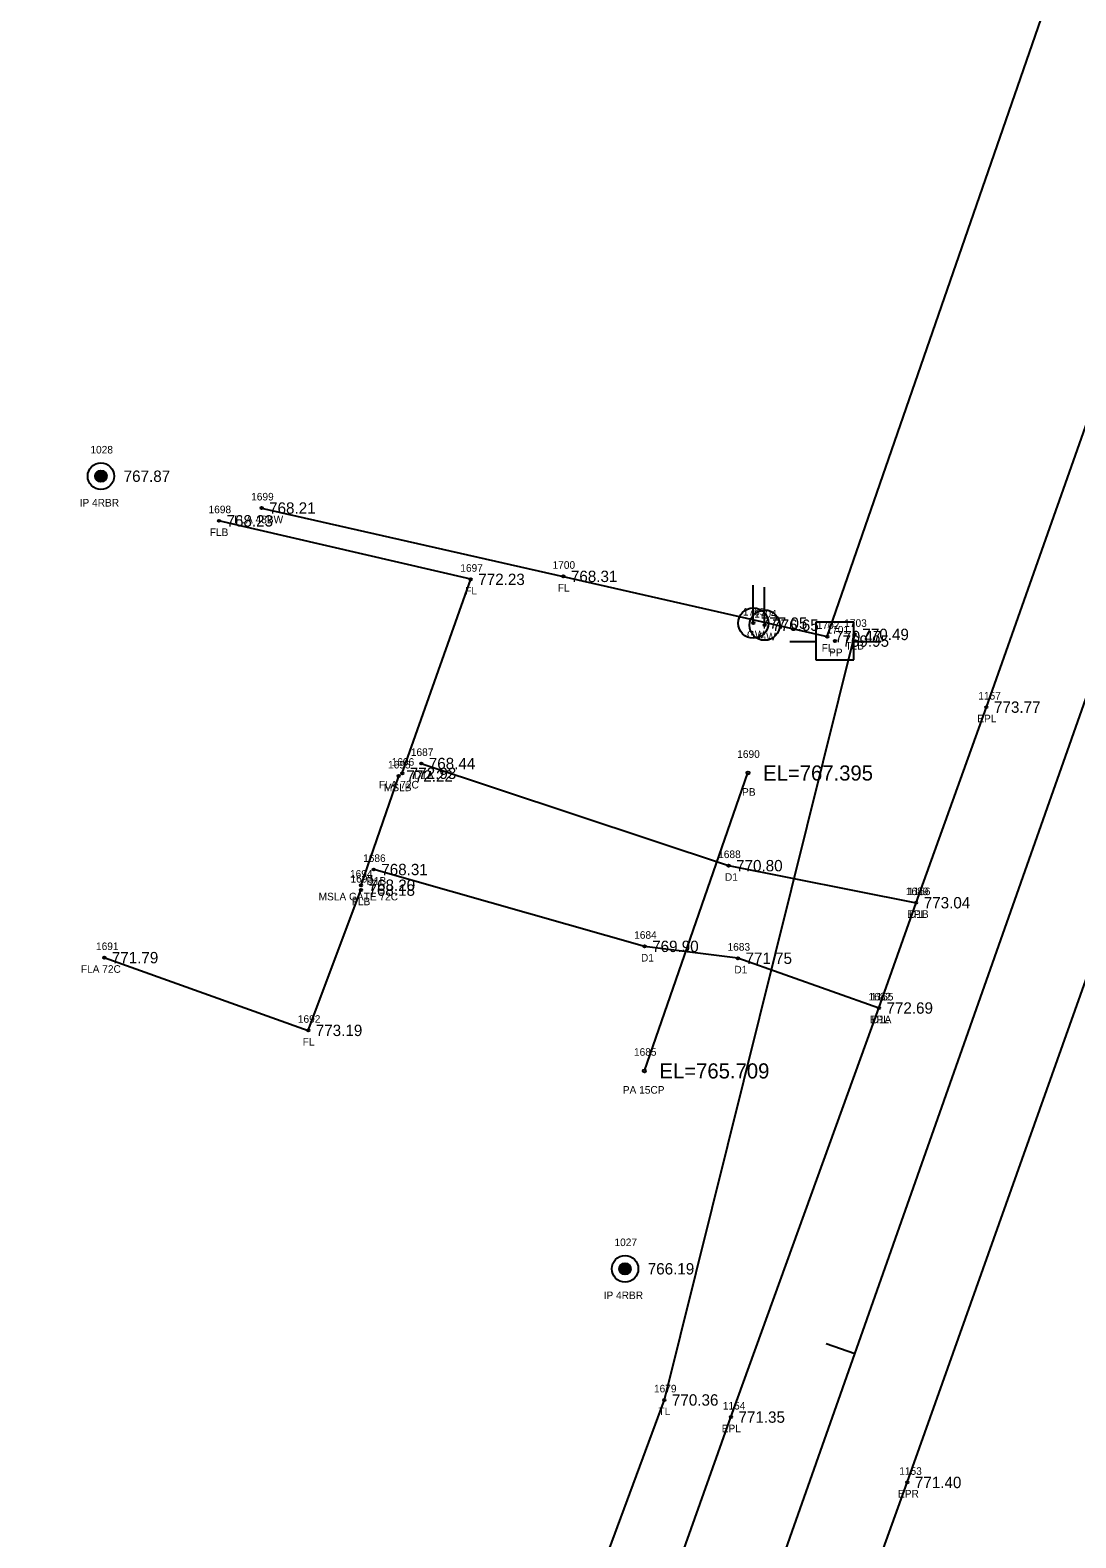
# Model space of a CAD drawing. Extents: x 1736563 to 1738032, y 1150548 to 1154248.
# Drawn here: x 1737763.6 to 1737901.6, y 1153946.3 to 1154145.2 of the extents above; entities that cross this region are included whole.
import ezdxf

# ---------------------------------------------------------------- set-up
doc = ezdxf.new("R2010")
doc.units = 0
for name, color, linetype in [('RD_EX_DR_Pipe', 7, 'Continuous'), ('RD_EX_DR_Pipe_txCode', 7, 'Continuous'), ('RD_EX_Driveway', 7, 'Continuous'), ('RD_EX_Driveway_txCode', 7, 'Continuous'), ('RD_EX_DV_Prop_txCode', 7, 'Continuous'), ('RD_EX_DV_PropPin', 7, 'Continuous'), ('RD_EX_Fence_Other', 7, 'Continuous'), ('RD_EX_Fence_Other_txCode', 7, 'Continuous'), ('RD_EX_Misc', 7, 'Continuous'), ('RD_EX_Misc_txCode', 7, 'Continuous'), ('RD_EX_Road', 7, 'Continuous'), ('RD_EX_Road_txCode', 7, 'Continuous'), ('RD_EX_TX_Driveway_ELEV', 7, 'Continuous'), ('RD_EX_TX_DV_Prop_ELEV', 7, 'Continuous'), ('RD_EX_TX_Fence_Other_ELEV', 7, 'Continuous'), ('RD_EX_TX_Misc_ELEV', 7, 'Continuous'), ('RD_EX_TX_Road_ELEV', 7, 'Continuous'), ('RD_EX_TX_UT_ELEV', 7, 'Continuous'), ('RD_EX_TX_VEG_ELEV', 7, 'Continuous'), ('RD_EX_UT', 7, 'Continuous'), ('RD_EX_UT_txCode', 7, 'Continuous'), ('RD_EX_VEG', 7, 'Continuous'), ('RD_EX_VEG_txCode', 7, 'Continuous'), ('RD_HC_Cl', 7, 'Continuous'), ('RD_HC_Data_Tic', 7, 'Continuous'), ('RD_HC_Survey_ELEV', 7, 'Continuous'), ('RD_SMD_Locator', 7, 'Continuous'), ('RD_TX_Pipe_ElevEX', 7, 'Continuous')]:
    doc.layers.add(name, color=color, linetype=linetype)

msp = doc.modelspace()

# ---------------------------------------------------------------- linework, layer by layer
at = {"layer": 'RD_EX_DR_Pipe'}
msp.add_line((1737844.68, 1154007.88), (1737858.35, 1154047.2), dxfattribs=at)
at = {"layer": 'RD_EX_Driveway'}
for points in [[(1737815.24, 1154048.45), (1737855.79, 1154034.97), (1737880.55, 1154030.08)], [(1737875.63, 1154016.18), (1737857.03, 1154022.75), (1737844.71, 1154024.32), (1737808.97, 1154034.46)]]:
    msp.add_lwpolyline(points, dxfattribs=at)
at = {"layer": 'RD_EX_DV_PropPin'}
for p, q in [((1737772.24, 1154086.17), (1737772.24, 1154086.57)), ((1737772.28, 1154086.07), (1737772.28, 1154086.67)), ((1737772.31, 1154086), (1737772.31, 1154086.74)), ((1737772.35, 1154085.94), (1737772.35, 1154086.8)), ((1737772.38, 1154085.9), (1737772.38, 1154086.84)), ((1737772.42, 1154085.85), (1737772.42, 1154086.88)), ((1737772.45, 1154085.82), (1737772.45, 1154086.92)), ((1737772.49, 1154085.79), (1737772.49, 1154086.95)), ((1737772.52, 1154085.76), (1737772.52, 1154086.98)), ((1737772.56, 1154085.73), (1737772.56, 1154087)), ((1737772.59, 1154085.71), (1737772.59, 1154087.03)), ((1737772.63, 1154085.69), (1737772.63, 1154087.04)), ((1737772.66, 1154085.68), (1737772.66, 1154087.06)), ((1737772.7, 1154085.66), (1737772.7, 1154087.08)), ((1737772.73, 1154085.65), (1737772.73, 1154087.09)), ((1737772.77, 1154085.64), (1737772.77, 1154087.1)), ((1737772.8, 1154085.63), (1737772.8, 1154087.11)), ((1737772.84, 1154085.62), (1737772.84, 1154087.12)), ((1737772.87, 1154085.62), (1737772.87, 1154087.12)), ((1737772.91, 1154085.61), (1737772.91, 1154087.13)), ((1737772.94, 1154085.61), (1737772.94, 1154087.13)), ((1737772.98, 1154085.61), (1737772.98, 1154087.13)), ((1737773.01, 1154085.61), (1737773.01, 1154087.13)), ((1737773.05, 1154085.61), (1737773.05, 1154087.13)), ((1737773.08, 1154085.62), (1737773.08, 1154087.12)), ((1737773.12, 1154085.62), (1737773.12, 1154087.12)), ((1737773.15, 1154085.63), (1737773.15, 1154087.11)), ((1737773.19, 1154085.64), (1737773.19, 1154087.1)), ((1737773.22, 1154085.65), (1737773.22, 1154087.09)), ((1737773.26, 1154085.66), (1737773.26, 1154087.08)), ((1737773.29, 1154085.68), (1737773.29, 1154087.06)), ((1737773.33, 1154085.69), (1737773.33, 1154087.04)), ((1737773.36, 1154085.71), (1737773.36, 1154087.03)), ((1737773.4, 1154085.73), (1737773.4, 1154087)), ((1737773.43, 1154085.76), (1737773.43, 1154086.98)), ((1737773.47, 1154085.79), (1737773.47, 1154086.95)), ((1737773.5, 1154085.82), (1737773.5, 1154086.92)), ((1737773.54, 1154085.85), (1737773.54, 1154086.88)), ((1737773.57, 1154085.9), (1737773.57, 1154086.84)), ((1737773.61, 1154085.94), (1737773.61, 1154086.8)), ((1737773.64, 1154086), (1737773.64, 1154086.74)), ((1737773.68, 1154086.07), (1737773.68, 1154086.67)), ((1737773.71, 1154086.17), (1737773.71, 1154086.57)), ((1737841.39, 1153981.56), (1737841.39, 1153981.95)), ((1737841.43, 1153981.46), (1737841.43, 1153982.06)), ((1737841.46, 1153981.39), (1737841.46, 1153982.13)), ((1737841.5, 1153981.33), (1737841.5, 1153982.18)), ((1737841.53, 1153981.28), (1737841.53, 1153982.23)), ((1737841.57, 1153981.24), (1737841.57, 1153982.27)), ((1737841.6, 1153981.21), (1737841.6, 1153982.31)), ((1737841.64, 1153981.18), (1737841.64, 1153982.34)), ((1737841.67, 1153981.15), (1737841.67, 1153982.37)), ((1737841.71, 1153981.12), (1737841.71, 1153982.39)), ((1737841.74, 1153981.1), (1737841.74, 1153982.41)), ((1737841.78, 1153981.08), (1737841.78, 1153982.43)), ((1737841.81, 1153981.07), (1737841.81, 1153982.45)), ((1737841.85, 1153981.05), (1737841.85, 1153982.47)), ((1737841.88, 1153981.04), (1737841.88, 1153982.48)), ((1737841.92, 1153981.03), (1737841.92, 1153982.49)), ((1737841.95, 1153981.02), (1737841.95, 1153982.5)), ((1737841.99, 1153981.01), (1737841.99, 1153982.51)), ((1737842.02, 1153981), (1737842.02, 1153982.51)), ((1737842.06, 1153981), (1737842.06, 1153982.52)), ((1737842.09, 1153981), (1737842.09, 1153982.52)), ((1737842.13, 1153981), (1737842.13, 1153982.52)), ((1737842.16, 1153981), (1737842.16, 1153982.52)), ((1737842.2, 1153981), (1737842.2, 1153982.52)), ((1737842.23, 1153981), (1737842.23, 1153982.51)), ((1737842.27, 1153981.01), (1737842.27, 1153982.51)), ((1737842.3, 1153981.02), (1737842.3, 1153982.5)), ((1737842.34, 1153981.03), (1737842.34, 1153982.49)), ((1737842.37, 1153981.04), (1737842.37, 1153982.48)), ((1737842.41, 1153981.05), (1737842.41, 1153982.47)), ((1737842.44, 1153981.07), (1737842.44, 1153982.45)), ((1737842.48, 1153981.08), (1737842.48, 1153982.43)), ((1737842.51, 1153981.1), (1737842.51, 1153982.41)), ((1737842.55, 1153981.12), (1737842.55, 1153982.39)), ((1737842.58, 1153981.15), (1737842.58, 1153982.37)), ((1737842.62, 1153981.18), (1737842.62, 1153982.34)), ((1737842.65, 1153981.21), (1737842.65, 1153982.31)), ((1737842.69, 1153981.24), (1737842.69, 1153982.27)), ((1737842.72, 1153981.28), (1737842.72, 1153982.23)), ((1737842.76, 1153981.33), (1737842.76, 1153982.18)), ((1737842.79, 1153981.39), (1737842.79, 1153982.13)), ((1737842.83, 1153981.46), (1737842.83, 1153982.06)), ((1737842.86, 1153981.56), (1737842.86, 1153981.95))]:
    msp.add_line(p, q, dxfattribs=at)
for centre, radius in [((1737772.98, 1154086.37), 1.75), ((1737772.98, 1154086.37), 0.761), ((1737842.13, 1153981.76), 1.75), ((1737842.13, 1153981.76), 0.761)]:
    msp.add_circle(centre, radius, dxfattribs=at)
at = {"layer": 'RD_EX_Fence_Other'}
for points in [[(1737794.17, 1154082.17), (1737833.99, 1154073.15), (1737868.81, 1154065.21), (1737901.32, 1154159.11)], [(1737812.73, 1154047.16), (1737821.77, 1154072.76), (1737788.55, 1154080.48)], [(1737773.41, 1154022.83), (1737800.33, 1154013.23), (1737807.28, 1154031.74)]]:
    msp.add_lwpolyline(points, dxfattribs=at)
at = {"layer": 'RD_EX_Misc'}
msp.add_line((1737807.3, 1154032.39), (1737812.28, 1154046.8), dxfattribs=at)
at = {"layer": 'RD_EX_Road'}
for points in [[(1737496.36, 1152940.55), (1737529.37, 1153032.75), (1737537.93, 1153057.4), (1737549.32, 1153089.17), (1737563.01, 1153127.73), (1737595.49, 1153219.95), (1737628.15, 1153312.67), (1737660.2, 1153403.8), (1737692.32, 1153495.67), (1737724.61, 1153587.75), (1737756.73, 1153679.29), (1737770.32, 1153718.5), (1737778.01, 1153740.46), (1737788.96, 1153772.48), (1737822.56, 1153867.79), (1737856.1, 1153962.19), (1737875.63, 1154016.18), (1737880.55, 1154030.08), (1737889.82, 1154055.89), (1737923.73, 1154151.97)], [(1737767.23, 1153635.63), (1737779.62, 1153670.7), (1737786.15, 1153689.96), (1737811.86, 1153764.64), (1737841.92, 1153849.66), (1737845.41, 1153858.54), (1737858.39, 1153893.35), (1737872.4, 1153934.23), (1737879.38, 1153953.57), (1737912.95, 1154048.07), (1737946.82, 1154144.4)]]:
    msp.add_lwpolyline(points, dxfattribs=at)
at = {"layer": 'RD_EX_UT'}
for p, q in [((1737859.06, 1154066.98), (1737859.06, 1154071.98)), ((1737860.55, 1154066.71), (1737860.55, 1154071.71)), ((1737872.32, 1154067.12), (1737867.32, 1154067.12)), ((1737867.32, 1154067.12), (1737867.32, 1154062.12)), ((1737872.32, 1154062.12), (1737872.32, 1154067.12)), ((1737863.89, 1154064.55), (1737867.36, 1154064.55)), ((1737872.25, 1154064.55), (1737875.89, 1154064.55)), ((1737867.32, 1154062.12), (1737872.32, 1154062.12))]:
    msp.add_line(p, q, dxfattribs=at)
for centre in [(1737859.06, 1154066.98), (1737860.55, 1154066.71)]:
    msp.add_circle(centre, 2, dxfattribs=at)
at = {"layer": 'RD_EX_VEG'}
msp.add_lwpolyline([(1737451.48, 1152925.19), (1737471.83, 1152967.5), (1737483.5, 1153062.03), (1737523.53, 1153143.47), (1737578.4, 1153225.34), (1737613.35, 1153318.74), (1737643.94, 1153407.18), (1737681, 1153500.22), (1737713.81, 1153596.51), (1737742.54, 1153686.46), (1737776.37, 1153777.24), (1737812.9, 1153871.37), (1737847.32, 1153964.45), (1737872.45, 1154065.49)], dxfattribs=at)
at = {"layer": 'RD_HC_Cl'}
msp.add_line((1736879.96, 1151154.46), (1737935.1, 1154148.31), dxfattribs=at)
at = {"layer": 'RD_HC_Data_Tic'}
msp.add_line((1737872.45, 1153970.53), (1737868.67, 1153971.86), dxfattribs=at)
at = {"layer": 'RD_SMD_Locator'}
for centre, radius in [((1737772.98, 1154086.37), 0.15), ((1737794.17, 1154082.17), 0.15), ((1737788.55, 1154080.48), 0.15), ((1737821.77, 1154072.76), 0.15), ((1737833.99, 1154073.15), 0.15), ((1737859.06, 1154066.98), 0.15), ((1737860.55, 1154066.71), 0.15), ((1737868.81, 1154065.21), 0.15), ((1737869.83, 1154064.61), 0.15), ((1737872.45, 1154065.49), 0.15), ((1737889.82, 1154055.89), 0.15), ((1737815.24, 1154048.45), 0.15), ((1737812.28, 1154046.8), 0.15), ((1737812.73, 1154047.16), 0.15), ((1737858.35, 1154047.2), 0.2), ((1737808.97, 1154034.46), 0.15), ((1737855.79, 1154034.97), 0.15), ((1737807.3, 1154032.39), 0.15), ((1737807.28, 1154031.74), 0.15), ((1737880.55, 1154030.08), 0.15), ((1737880.55, 1154030.08), 0.15), ((1737773.41, 1154022.83), 0.15), ((1737844.71, 1154024.32), 0.15), ((1737857.03, 1154022.75), 0.15), ((1737875.63, 1154016.18), 0.15), ((1737875.63, 1154016.18), 0.15), ((1737800.33, 1154013.23), 0.15), ((1737844.68, 1154007.88), 0.2), ((1737842.13, 1153981.76), 0.15), ((1737847.32, 1153964.45), 0.15), ((1737856.1, 1153962.19), 0.15), ((1737879.38, 1153953.57), 0.15)]:
    msp.add_circle(centre, radius, dxfattribs=at)

# ---------------------------------------------------------------- texts
at = {"layer": 'RD_EX_DR_Pipe_txCode'}
for s, p in [('1690', (1737856.94, 1154049.2)), ('PB', (1737857.57, 1154044.2)), ('1685', (1737843.31, 1154009.88)), ('PA 15CP', (1737841.84, 1154004.88))]:
    msp.add_text(s, height=1, dxfattribs=at).set_placement(p)
at = {"layer": 'RD_EX_Driveway_txCode'}
for s, p in [('1687', (1737813.87, 1154049.45)), ('D1A', (1737814.28, 1154046.45)), ('1686', (1737807.57, 1154035.46)), ('1688', (1737854.42, 1154035.97)), ('D1B', (1737808.02, 1154032.46)), ('D1', (1737855.32, 1154032.97)), ('1689', (1737879.18, 1154031.08)), ('D1B', (1737879.6, 1154028.08)), ('1684', (1737843.34, 1154025.32)), ('1683', (1737855.66, 1154023.75)), ('D1', (1737844.24, 1154022.32)), ('D1', (1737856.56, 1154020.75)), ('1682', (1737874.26, 1154017.18)), ('D1A', (1737874.67, 1154014.18))]:
    msp.add_text(s, height=1, dxfattribs=at).set_placement(p)
at = {"layer": 'RD_EX_DV_Prop_txCode'}
for s, p in [('1028', (1737771.59, 1154089.37)), ('IP 4RBR', (1737770.17, 1154082.37)), ('1027', (1737840.74, 1153984.76)), ('IP 4RBR', (1737839.31, 1153977.76))]:
    msp.add_text(s, height=1, dxfattribs=at).set_placement(p)
at = {"layer": 'RD_EX_Fence_Other_txCode'}
for s, p in [('1698', (1737787.18, 1154081.48)), ('1699', (1737792.8, 1154083.17)), ('FLA 48BW', (1737790.56, 1154080.17)), ('FLB', (1737787.34, 1154078.48)), ('1697', (1737820.4, 1154073.76)), ('1700', (1737832.57, 1154074.15)), ('FL', (1737821.04, 1154070.76)), ('FL', (1737833.26, 1154071.15)), ('1702', (1737867.43, 1154066.21)), ('FL', (1737868.08, 1154063.21)), ('1696', (1737811.34, 1154048.16)), ('FLA 72C', (1737809.65, 1154045.16)), ('1693', (1737805.91, 1154032.74)), ('FLB', (1737806.07, 1154029.74)), ('1691', (1737772.33, 1154023.83)), ('FLA 72C', (1737770.33, 1154020.83)), ('1692', (1737798.96, 1154014.23)), ('FL', (1737799.6, 1154011.23))]:
    msp.add_text(s, height=1, dxfattribs=at).set_placement(p)
at = {"layer": 'RD_EX_Misc_txCode'}
for s, p in [('1695', (1737810.86, 1154047.8)), ('MSLB', (1737810.31, 1154044.8)), ('1694', (1737805.84, 1154033.39)), ('MSLA GATE 72C', (1737801.7, 1154030.39))]:
    msp.add_text(s, height=1, dxfattribs=at).set_placement(p)
at = {"layer": 'RD_EX_Road_txCode'}
for s, p in [('1157', (1737888.75, 1154056.89)), ('EPL', (1737888.61, 1154053.89)), ('1156', (1737879.46, 1154031.08)), ('EPL', (1737879.34, 1154028.08)), ('1155', (1737874.57, 1154017.18)), ('EPL', (1737874.43, 1154014.18)), ('1154', (1737855.03, 1153963.19)), ('EPL', (1737854.89, 1153960.19)), ('1153', (1737878.32, 1153954.57)), ('EPR', (1737878.15, 1153951.57))]:
    msp.add_text(s, height=1, dxfattribs=at).set_placement(p)
at = {"layer": 'RD_EX_TX_Driveway_ELEV'}
for s, p in [('768.44', (1737816.24, 1154047.7)), ('768.31', (1737809.97, 1154033.71)), ('770.80', (1737856.79, 1154034.22)), ('773.04', (1737881.55, 1154029.33)), ('769.90', (1737845.71, 1154023.57)), ('771.75', (1737858.03, 1154022)), ('772.69', (1737876.63, 1154015.43))]:
    msp.add_text(s, height=1.5, dxfattribs=at).set_placement(p)
at = {"layer": 'RD_EX_TX_DV_Prop_ELEV'}
for s, p in [('767.87', (1737775.98, 1154085.62)), ('766.19', (1737845.13, 1153981.01))]:
    msp.add_text(s, height=1.5, dxfattribs=at).set_placement(p)
at = {"layer": 'RD_EX_TX_Fence_Other_ELEV'}
for s, p in [('768.21', (1737795.17, 1154081.42)), ('768.23', (1737789.55, 1154079.73)), ('772.23', (1737822.77, 1154072.01)), ('768.31', (1737834.99, 1154072.4)), ('770.47', (1737869.81, 1154064.46)), ('772.93', (1737813.73, 1154046.41)), ('768.18', (1737808.28, 1154030.99)), ('771.79', (1737774.41, 1154022.08)), ('773.19', (1737801.33, 1154012.48))]:
    msp.add_text(s, height=1.5, dxfattribs=at).set_placement(p)
at = {"layer": 'RD_EX_TX_Misc_ELEV'}
for s, p in [('772.22', (1737813.28, 1154046.05)), ('768.20', (1737808.3, 1154031.64))]:
    msp.add_text(s, height=1.5, dxfattribs=at).set_placement(p)
at = {"layer": 'RD_EX_TX_Road_ELEV'}
for s, p in [('773.77', (1737890.82, 1154055.14)), ('773.04', (1737881.55, 1154029.33)), ('772.69', (1737876.63, 1154015.43)), ('771.35', (1737857.1, 1153961.44)), ('771.40', (1737880.38, 1153952.82))]:
    msp.add_text(s, height=1.5, dxfattribs=at).set_placement(p)
at = {"layer": 'RD_EX_TX_UT_ELEV'}
for s, p in [('777.05', (1737860.06, 1154066.23)), ('776.65', (1737861.55, 1154065.96))]:
    msp.add_text(s, height=1.5, dxfattribs=at).set_placement(p)
at = {"layer": 'RD_EX_TX_VEG_ELEV'}
for s, p in [('770.49', (1737873.45, 1154064.74)), ('770.36', (1737848.32, 1153963.7))]:
    msp.add_text(s, height=1.5, dxfattribs=at).set_placement(p)
at = {"layer": 'RD_EX_UT_txCode'}
for s, p in [('1705', (1737857.68, 1154067.98)), ('1704', (1737859.16, 1154067.71)), ('1701', (1737868.72, 1154065.61)), ('GW', (1737858.22, 1154064.98)), ('GW', (1737859.71, 1154064.71)), ('PP', (1737869.05, 1154062.61))]:
    msp.add_text(s, height=1, dxfattribs=at).set_placement(p)
at = {"layer": 'RD_EX_VEG_txCode'}
for s, p in [('1703', (1737871.06, 1154066.49)), ('TLB', (1737871.2, 1154063.49)), ('1679', (1737845.95, 1153965.45)), ('TL', (1737846.55, 1153962.45))]:
    msp.add_text(s, height=1, dxfattribs=at).set_placement(p)
at = {"layer": 'RD_HC_Survey_ELEV'}
msp.add_text('769.95', height=1.5, dxfattribs=at).set_placement((1737870.83, 1154063.86))
at = {"layer": 'RD_TX_Pipe_ElevEX'}
for s, p in [('EL=767.395', (1737860.35, 1154046.2)), ('EL=765.709', (1737846.68, 1154006.88))]:
    msp.add_text(s, height=2, dxfattribs=at).set_placement(p)

doc.saveas('drawing.dxf')
